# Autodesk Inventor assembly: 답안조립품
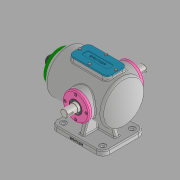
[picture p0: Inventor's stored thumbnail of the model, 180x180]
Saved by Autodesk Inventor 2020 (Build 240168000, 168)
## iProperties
Created: 2021-11
Part Number: 답안조립품
Document SubType Name: Assembly
Designer: Administrator
Author: Administrator
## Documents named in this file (14)
- C:\Users\Administrator\Desktop\711106V1031\답안조립품.iam
- C:\Users\Administrator\Desktop\711106V1031\본체.ipt
- C:\Users\Administrator\Desktop\711106V1031\베어링 6205.ipt
- 베어링 6205.ipt
- C:\Users\Administrator\Desktop\711106V1031\볼트 M4x0.7.ipt
- C:\Users\Administrator\Desktop\711106V1031\부시.ipt
- C:\Users\Administrator\Desktop\711106V1031\상부커버.ipt
- C:\Users\Administrator\Desktop\711106V1031\슬라이드 커버.ipt
- C:\Users\Administrator\Desktop\711106V1031\슬라이드.ipt
- C:\Users\Administrator\Desktop\711106V1031\오일실.ipt
- 오일실.ipt
- C:\Users\Administrator\Desktop\711106V1031\육각머리볼트 M4.ipt
- C:\Users\Administrator\Desktop\711106V1031\축 커버.ipt
- C:\Users\Administrator\Desktop\711106V1031\편심축.ipt
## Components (12 placed, 1 different names)
1. M4x0.7:2 — 각도:7
2. M4x0.7:4
3. M4x0.7:5
4. M4x0.7:6
5. M4x0.7:1 — 각도:5
6. M4x0.7:7
7. M4x0.7:8
8. M4x0.7:9
9. M4x0.7:3 — 각도:6
10. M4x0.7:10
11. M4x0.7:11
12. M4x0.7:12
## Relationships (3: Angle 3)
- 각도:5 [Angle]: M4x0.7:1
- 각도:6 [Angle]: M4x0.7:3
- 각도:7 [Angle]: M4x0.7:2
